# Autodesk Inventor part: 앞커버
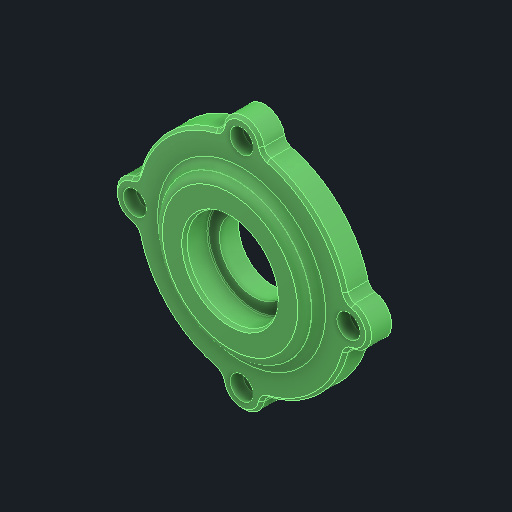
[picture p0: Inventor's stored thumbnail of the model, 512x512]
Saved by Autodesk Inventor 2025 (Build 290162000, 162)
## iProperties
Created: 2025-08
Part Number: 앞커버
Material: 알루미늄 6061
Document SubType Name: Modeling
Designer: infra08
Density: 2.71 g/cm^3
Appearance: 기본값
Company: 한국ATC센터
Author: jhkim
Sending System: Autodesk Inventor 2026
Preprocessor: ST-DEVELOPER v20.1
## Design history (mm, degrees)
feature "솔리드1"
node "솔리드2"
